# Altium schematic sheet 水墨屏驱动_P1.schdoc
size 297 x 209 mm; Symbol: Drawing-Symbol_A4; Company: 嘉立创EDA; Version: V1.0; Page Size: A4; @Project Name: 水墨屏demo1; @Page Count: 1; @Update Date: 2026-03-01; @Create Date: 2026-03-01; @Schematic Name: Schematic1; @Page No: 1; @Page Name: P1; Device: Drawing-Symbol_A4; @Board Name: Board1; @Create Time: 12:03:36; @Update Time: 12:03:36; @Assembly Variant: Basic; Border: 1; Title Block Position: 3; Size: A4; Width: 1170; Height: 825; Region Start: 1; X Region Count: 6; Y Region Count: 4; Blade Width: 10
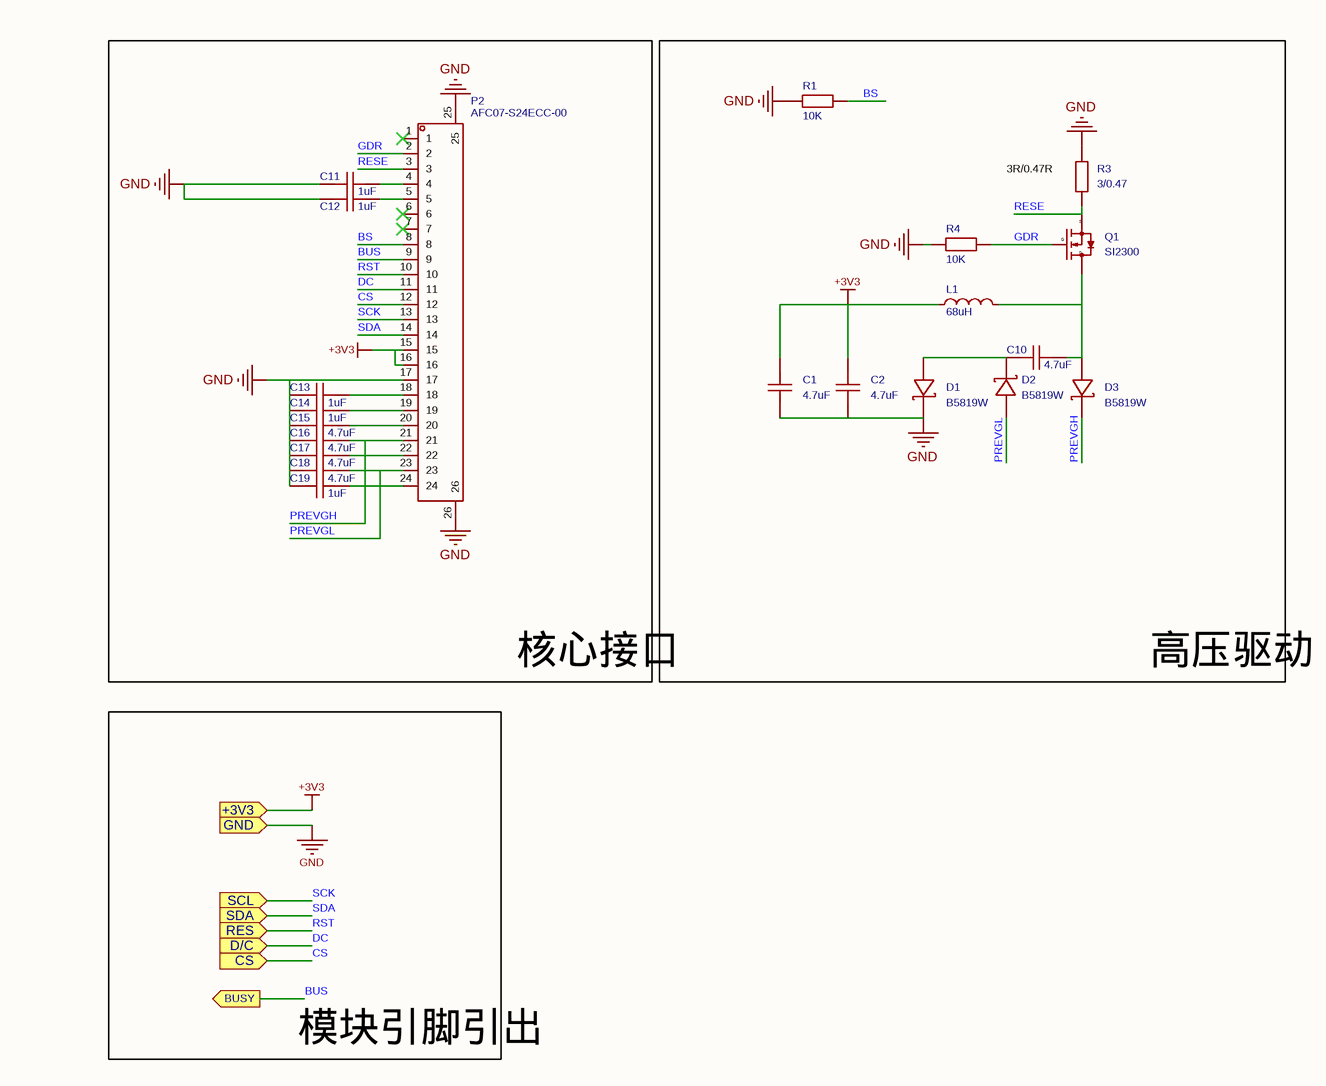
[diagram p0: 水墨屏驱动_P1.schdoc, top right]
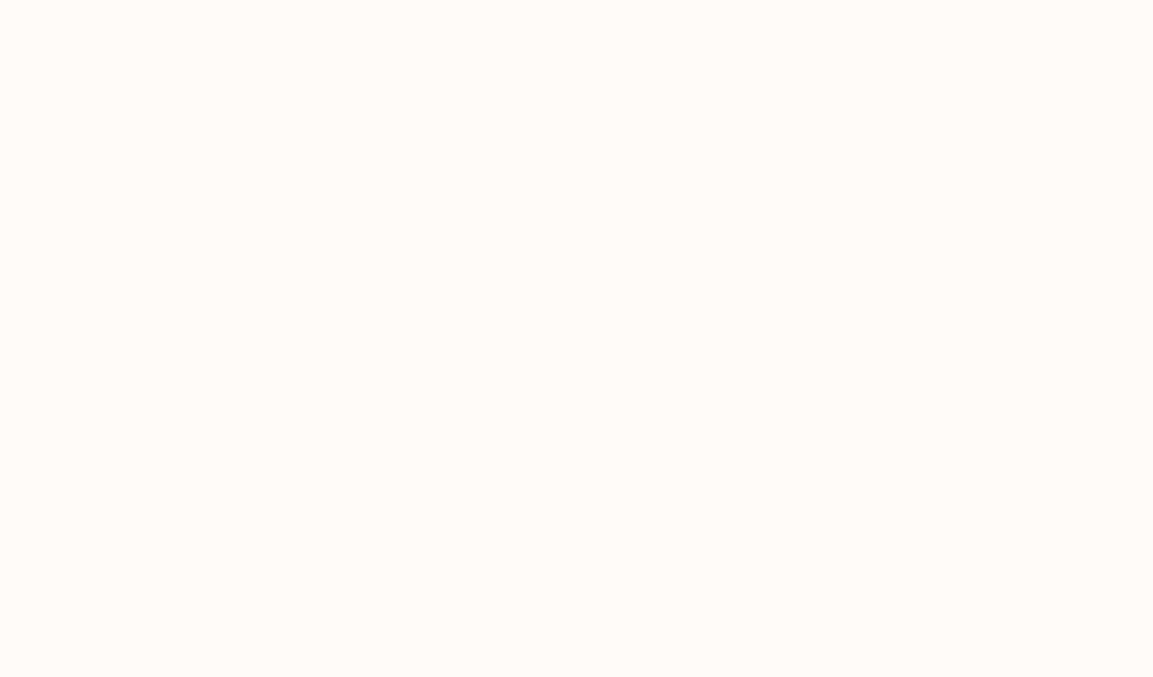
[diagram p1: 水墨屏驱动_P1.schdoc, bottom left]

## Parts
C1  4.7uF  [C0603]
C2  4.7uF  [C0603]
C10  4.7uF  [C0603]
C11  1uF  [C0603]
C12  1uF  [C0603]
C13  1uF  [C0603]
C14  1uF  [C0603]
C15  4.7uF  [C0603]
C16  4.7uF  [C0603]
C17  4.7uF  [C0603]
C18  4.7uF  [C0603]
C19  1uF  [C0603]
D1  B5819W  [SOD-123_L2.8-W1.8-LS3.7-RD]
D2  B5819W  [SOD-123_L2.8-W1.8-LS3.7-RD]
D3  B5819W  [SOD-123_L2.8-W1.8-LS3.7-RD]
L1  68uH  [IND-SMD_L11.5-W10.5_SRG1040]
P2  AFC07-S24ECC-00  [FPC-SMD_24P-L17.5-W5.4-P0.50]
Q1  SI2300  [SOT-23-3_L2.9-W1.3-P1.90-LS2.4-BR]
R1  10K  [R0603]
R3  3/0.47  [R0603]
R4  10K  [R0603]

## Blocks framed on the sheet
核心接口: C11-C19 P2
高压驱动: C1 C2 C10 D1-D3 L1 Q1 R1 R3 R4

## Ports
+3V3 (in), BUSY (out), CS (in), D/C (in), GND (in), RES (in), SCL (in), SDA (in)

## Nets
+3V3: C1.2 C2.2 L1.1 P2.15 P2.16 ; port +3V3
GND: C1.1 C2.1 C11.1 C12.1 C13.1 C14.1 C15.1 C16.1 C17.1 C18.1 C19.1 D1.1(K) P2.17 P2.25 P2.26 R1.1 R3.2 R4.1 ; port GND
BS: P2.8 R1.2
BUS: P2.9 ; port BUSY
CS: P2.12 ; port CS
DC: P2.11 ; port D/C
GDR: P2.2 Q1.1(G) R4.2
PREVGH: C16.2 D3.1(K) P2.21
PREVGL: C18.2 D2.2(A) P2.23
RESE: P2.3 Q1.2(S) R3.1
RST: P2.10 ; port RES
SCK: P2.13 ; port SCL
SDA: P2.14 ; port SDA
NetC10_1: C10.1 D1.2(A) D2.1(K)
NetC10_2: C10.2 D3.2(A) L1.2 Q1.3(D)
NetC11_2: C11.2 P2.4
NetC12_2: C12.2 P2.5
NetC13_2: C13.2 P2.18
NetC14_2: C14.2 P2.19
NetC15_2: C15.2 P2.20
NetC17_2: C17.2 P2.22
NetC19_2: C19.2 P2.24

Not connected (* = marked no-connect by the designer): P2 1* 6* 7*

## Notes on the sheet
- (near R3) 3R/0.47R
- 模块引脚引出

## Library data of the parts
C1 C2 C10-C19 = CAP_0603: Symbol: CapAcitance; 3D Model: ac125912035d415993ca9572d50418b1; 3D Model Transform: 62.992,31.496,0,0,0,0,0,0,0; ConvertToPcb: yes; ModelName: C0603_L1.6-W0.8-H0.8
D1-D3 = B5819W_C64885: 直流反向耐压(Vr):40V;平均整流电流(Io):1A;正向压降(Vf):600mV@1A;; Manufacturer: MDD; 3D Model: 7884390a25fb4c08947731ebfba7e3f8; 3D Model Transform: 144.8816,62.992,0,0,0,0,0,0,0; Reverse Voltage (Vr): 40V; Average Rectified Current (Io): 1A; AddInBom: yes
L1 = SRG1040-680-M: 电感值:68uH;精度:±20%;额定电流:2A;饱和电流(Isat):3A;类型:一体成型电感;; Manufacturer: JIERR(捷而瑞); 3D Model: 60d6566a84cc4ef9a23d25fbddc8792e0819f05c4eef4c71ace90d822a990e87; 3D Model Transform: 452.755,413.7787,0,0,0,0,-1.184,-2.756,0; Tolerance: ±20%; Current Rating: 2A; Current - Saturation(Isat): 3A; DC Resistance(DCR): 260mΩ; Type: 一体成型电感; AddInBom: yes
P2 = AFC07-S24ECC-00: 锁定特性:抽屉式;触点类型:上接;触点数量:24P;间距:0.5mm;安装方式:卧贴;工作温度:-25℃~+85℃;; Manufacturer: JS(钜硕电子); Symbol: FPC 0.5MM 24P Pull type H2.0mm Pick up; AddInBom: yes; ModelId: a48accf5b63741de99e6989a1a8045a70819f05c4eef4c71ace90d822a990e87; ModelTransform: 692.912,216.535,0,0,0,0,0,-54.173,0; Locking Feature: 抽屉式; Number of Contacts: 24P; Pitch: 0.5mm; FFC, FCB Thickness: 0.3mm; Rated Voltage (Max): 50V; Current Rating (Max): 400mA
Q1 = SI2300_C181085: 类型:N沟道;漏源电压(Vdss):20V;连续漏极电流(Id):5A;功率(Pd):-;导通电阻(RDS(on)@Vgs,Id):60mΩ@2.5V,4A;阈值电压(Vgs(th)@Id):1.5V@250uA;; Manufacturer: Hottech(合科泰); 3D Model: c62791f0466c4ae2a892c056b845b0ca; 3D Model Transform: 98.425,114.173,0,180,0,0,0.0005,-0.0005,0; Type: N沟道; Drain Source Voltage (Vdss): 20V; Continuous Drain Current (Id): 5A; AddInBom: yes; ModelName: SOT-23-3P_L2.9-W1.3-H1.0-LS2.4-P0.95
R1 R3 R4 = Res_0603: Symbol: 电阻; 3D Model: fc143cca1e79419f9cd78b61e9279f08; 3D Model Transform: 31.8897,63.7794,0,90,0,0,0,0,0; ConvertToPcb: yes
